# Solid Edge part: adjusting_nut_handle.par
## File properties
Title: Adjusting nut handle
Author: Abhinav Rai
Template: Normal.par
Last saved by: CADCIM
Revision: 16
Application: Solid Edge
Accuracy: 0.99
Material: aluminum
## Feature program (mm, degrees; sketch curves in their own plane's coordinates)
sketch for "unnamed Protrusion 1" plane through (0, 0, 0) normal (0, -1, 0) x-axis (1, 0, 0)
  circle centre (0, 0) radius 9.5123
extrude "unnamed Protrusion 1" add finite 127 symmetric
chamfer "Chamfer_1" setback 1.5748
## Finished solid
Body 1: solid body, 5 faces, 4 edges, 0 vertices.
  Faces by surface: cone 2, plane 2, cylinder 1
  Edges by curve: circle 4
Bounding box of the edges (mm): 19.025 x 127.000 x 19.025, from (-9.5123, -63.5, -9.5123) to (9.5123, 63.5, 9.5123).
Cylindrical faces by radius (mm): R9.5123 x1
Conical faces (half-angle, radius in mm at the cone's reference point): 45 deg R7.9375 x1, 45 deg R9.5123 x1
Planar faces by outward normal: +y 1, -y 1
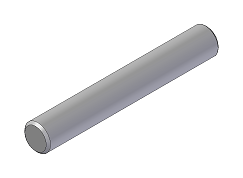
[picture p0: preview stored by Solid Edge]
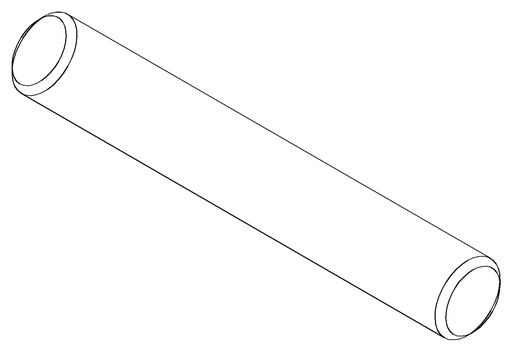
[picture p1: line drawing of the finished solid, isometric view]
